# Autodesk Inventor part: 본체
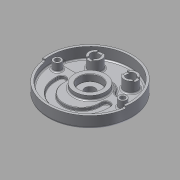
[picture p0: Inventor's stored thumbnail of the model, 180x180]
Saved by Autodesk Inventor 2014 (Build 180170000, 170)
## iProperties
Created: 2015-06
Part Number: 본체
Material: 알루미늄 6061
Document SubType Name: Modeling
Designer: MYHOME
Mass: 1076.63 g
Surface Area: 1037.64 cm^2
Volume: 397.279 cm^3
Density: 2.71 g/cm^3
Appearance: 알루미늄 - 평지
Author: MYHOME
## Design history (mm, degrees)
sketch "스케치1"
  geometry: C1 r 95 at (0, 0); C2 r 90 at (0, 0); 1 further point
  constraints: 2 centre point, 2 coincident
  dimensions: "d0" = 190 diameter of C1; "d1" = 180 diameter of C2
extrude "돌출1" new body sketch "스케치1" distance "d2" = 32; taper "d3" = 0 deg
extrude "돌출2" join sketch "스케치1" distance "d4" = 7; taper "d5" = 0 deg
sketch "스케치3"
  geometry: L1 (-88.566, 16)-(88.566, 16); A1 r 90 centre (0, 0) between (88.566, 16) and (-88.566, 16) reference; A2 r 42 centre (0, 0) between (-38.833, 16) and (38.833, 16)
  constraints: 4 point on circle, 2 end point, 2 point on line, 1 centre point, 1 coincident, 1 horizontal
  dimensions: "d11" = 16 distance from line of A1.centre L1; "d12" = 84 diameter of A2
extrude "돌출4" join sketch "스케치3" distance "d13" = 7; taper "d14" = 0 deg
fillet "모깎기2" dims "d15" = 10
sketch "스케치4"
  geometry: C1 r 15 at (-40, 52); C2 r 15 at (40, 52); A1 r 90 centre (0, 0) between (85.114, 29.25) and (-85.114, 29.25) reference
  constraints: 2 centre point, 1 horizontal alignment
  dimensions: "d16" = 30 diameter of C1; "d17" = 30 diameter of C2; "d18" = 52 vertical distance of A1.centre C2.centre; "d19" = 40 horizontal distance of A1.centre C1.centre; "d20" = 80 distance of C2.centre C1.centre
extrude "돌출5" join sketch "스케치4" distance "d21" = 25; taper "d22" = 0 deg
sketch "스케치5"
  geometry: C1 r 15 at (0, 0) reference; C2 r 15 at (80, 0) reference; C3 r 10 at (0, 0); C4 r 10 at (80, 0); 1 further point
  constraints: 2 centre point, 2 coincident
  dimensions: "d23" = 20 diameter of C3; "d24" = 20 diameter of C4
extrude "돌출6" cut sketch "스케치5" stored distance "d25" = 25; taper "d26" = 0 deg
sketch "스케치6"
  geometry: L1 (-6, 15)-(6, 15); L2 (6, 15)-(6, -15); L3 (6, -15)-(-6, -15); L4 (-6, -15)-(-6, 15); L5 (65, 6)-(95, 6); L6 (95, 6)-(95, -6); L7 (95, -6)-(65, -6); L8 (65, -6)-(65, 6); C1 r 10 at (0, 0) reference; C2 r 15 at (0, 0) reference; C3 r 10 at (80, 0) reference; C4 r 15 at (80, 0) reference; C5 r 15 at (80, 0) reference; 3 further points
  constraints: 16 end point, 4 parallel, 4 tangent, 2 horizontal, 2 midpoint, 2 perpendicular, 1 horizontal alignment, 1 vertical alignment
  dimensions: "d27" = 12 distance of L2.end L3.end; "d28" = 12 distance of L5.end L6.end
extrude "돌출7" cut sketch "스케치6" distance "d29" = 3; taper "d30" = 0 deg
sketch "스케치7"
  geometry: L1 (75.657, 16)-(45.033, 16) reference; L2 (41, -19)-(59, -19); L3 (-41, -19)-(-59, -19); L4 (-41, -14)-(-59, -14); L5 (41, -14)-(59, -14); L6 (-41, -19)-(-41, -14); L7 (-59, -19)-(-59, -14); L8 (41, -19)-(41, -14); L9 (59, -19)-(59, -14); A1 r 42 centre (0, 0) between (36.373, 21) and (-36.373, 21) reference; A2 r 50 centre (0, -19) between (-50, -19) and (50, -19); A3 r 59 centre (0, -19) between (-59, -19) and (59, -19); A4 r 41 centre (0, -19) between (-41, -19) and (41, -19); A5 r 9 centre (-50, -19) between (-41, -19) and (-59, -19); A6 r 9 centre (50, -19) between (59, -19) and (41, -19); A7 r 9 centre (-50, -14) between (-41, -14) and (-59, -14); A8 r 9 centre (50, -14) between (59, -14) and (41, -14)
  constraints: 16 end point, 14 point on circle, 9 tangent, 7 centre point, 3 parallel, 2 midpoint, 1 collinear, 1 perpendicular, 1 vertical alignment
  dimensions: "d33" = 19 distance of A1.centre A2.centre; "d34" = 41 radius of A4; "d35" = 59 radius of A3; "d36" = 5 distance between parallel lines of L3 L4; "d37" = 5 distance between parallel lines of L2 L5
extrude "돌출8" cut sketch "스케치7" distance "d38" = 7; taper "d39" = 0 deg
chamfer "모따기1" distance "d40" = 1; stored, may be unused: second distance "d41" = 2, angle "d42" = 45 deg
fillet "모깎기3" dims "d43" = 1
sketch "스케치8"
  geometry: C1 r 35 at (0, 0); A1 r 90 centre (0, 0) between (-85.114, 29.25) and (85.114, 29.25) reference
  constraints: 1 centre point, 1 coincident
  dimensions: "d44" = 70 diameter of C1
extrude "돌출9" join sketch "스케치8" distance "d45" = 10; taper "d46" = 0 deg
fillet "모깎기4" dims "d47" = 3
sketch "스케치9"
  geometry: C1 r 35 at (0, 0) reference; 1 further point
  constraints: 1 coincident
hole "구멍1" sketch "스케치9" at (0, 0) diameter "d48" = 23; stored, may be unused: countersink angle "d52" = 90 deg, drill point angle "d54" = 0 deg; dims "d49" = 6, "d50" = 50, "d51" = 15, "d53" = 8
fillet "모깎기5" dims "d58" = 0.3
sketch "스케치10"
  geometry: C1 r 9 at (-74, 0); C2 r 9 at (74, 0); A1 r 42 centre (0, 0) between (36.373, 21) and (-36.373, 21) reference
  constraints: 2 centre point, 2 horizontal alignment
  dimensions: "d59" = 18 diameter of C1; "d60" = 18 diameter of C2; "d61" = 74 distance of C1.centre A1.centre; "d62" = 148 distance of C2.centre C1.centre
extrude "돌출10" join sketch "스케치10" stored distance "d63" = 10; taper "d64" = 0 deg
fillet "모깎기6" dims "d65" = 3
sketch "스케치11"
  geometry: C1 r 9 at (74, 0) reference; C2 r 9 at (-74, 0) reference; 2 further points
  constraints: 2 coincident
hole "구멍2" sketch "스케치11" at (-74, 0), (74, 0) diameter "d66" = 11; stored, may be unused: countersink angle "d70" = 90 deg, drill point angle "d72" = 0 deg; dims "d67" = 6, "d68" = 18, "d69" = 11, "d71" = 8
sketch "스케치12"
  geometry: L1 (-94.075, -13.221)-(0, 0); L2 (0, 0)-(94.075, -13.221); L3 (0, 0)-(90, 0); L4 (0, 0)-(-90, 0); A1 r 90 centre (0, 0) between (90, 0) and (-90, 0) reference; A2 r 95 centre (0, 0) between (94.075, -13.221) and (-94.075, -13.221) reference; 2 further points
  constraints: 8 end point, 6 point on circle, 2 point on line, 1 collinear, 1 horizontal
  dimensions: "d73" = 8 deg angle of L3 L2; "d74" = 8 deg angle of L4 L1
extrude "돌출11" cut sketch "스케치12" distance "d75" = 5; taper "d76" = 0 deg
fillet "모깎기7" dims "d77" = 3
fillet "모깎기8" dims "d78" = 3
fillet "모깎기9" dims "d79" = 5
fillet "모깎기10" dims "d80" = 3
sketch "스케치13"
  geometry: C1 r 90 at (0, 0) reference; A1 r 68 centre (0, 0) between (0, -68) and (68, 0)
  constraints: 2 point on circle, 1 centre point, 1 coincident, 1 other
  dimensions: "d81" = 68 radius of A1
feature "엠보싱1" sketch "스케치13" dims "d0" = 190, "d1" = 180, "d82" = 0.5, "d83" = 0
fillet "모깎기11" dims "d84" = 3
chamfer "모따기3" distance "d91" = 1; stored, may be unused: second distance "d92" = 2, angle "d93" = 45 deg
sketch "스케치16"
  geometry: C1 r 11.5 at (0, 0) reference; C2 r 26 at (0, 0)
  constraints: 1 centre point, 1 coincident
  dimensions: "d94" = 52 diameter of C2
extrude "돌출14" join sketch "스케치16" distance "d95" = 12; taper "d96" = -15 deg
sketch "스케치17"
  geometry: C1 r 22.785 at (0, 0) reference; C2 r 11.5 at (0, 0)
  constraints: 1 centre point, 1 coincident
  dimensions: "d97" = 23 diameter of C2
extrude "돌출15" cut sketch "스케치17" stored distance "d98" = 12; taper "d99" = 0 deg
fillet "모깎기12" dims "d100" = 1
fillet "모깎기13" dims "d101" = 3
node "솔리드1"
node "투영된 루프1"
